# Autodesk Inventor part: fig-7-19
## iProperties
Created: 2004-05
Part Number: fig-7-19
Document SubType Name: Modeling
Designer: CADCIM Technologies
Manufacturer: Standard
Standards Organization: Custom
Author: CADCIM Technologies
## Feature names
1. Extrusion1
2. Loft2
